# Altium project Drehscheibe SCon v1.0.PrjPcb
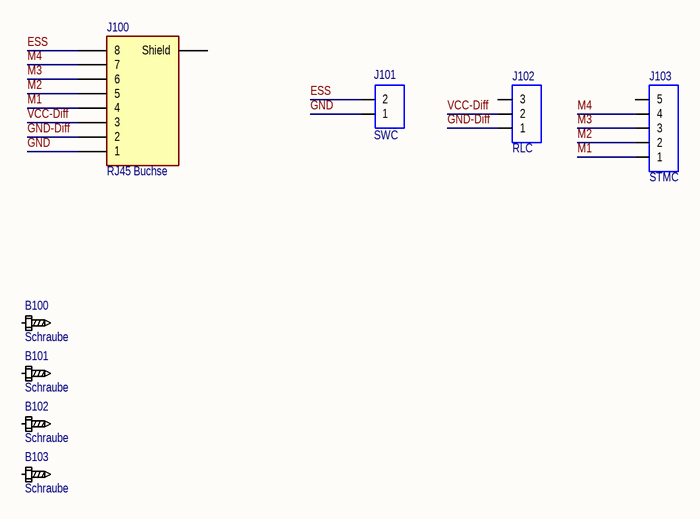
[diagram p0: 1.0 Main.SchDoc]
ZIP: A-3052; Web: www.pcsb.at; Version: v1.0; Title: Drehscheibe SCon; Street: Hauptstraße 47; Phone: 02774/29452; Number: 1; Email: office@pcsb.at; Drawnby2: SONP; Drawnby1: BRAL; Country: Austria; Company: PCSG; Client: Wolfgang Paris, Gerhard Abraham; City: Neustift-Innermanzing
1 sheet, 8 parts. Net scope: global (net labels, ports and power ports of the same name join across sheets).
Board file: PCB1.PcbDoc

## Sheet 1.0 Main.SchDoc: Drehscheibe SCon
size A4; SheetNumber: 1; SheetTotal: 1

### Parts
B100  Schraube  [B_Schraube-M3]
B101  Schraube  [B_Schraube-M3]
B102  Schraube  [B_Schraube-M3]
B103  Schraube  [B_Schraube-M3]
J100  RJ45 Buchse  [J_TE-RJ45-8L-B]
J101  SWC  [SIP-2]
J102  RLC  [Sip-3]
J103  STMC  [SIP-5]

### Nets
ESS: J100.8 J101.2
GND: J100.1 J101.1
GND-Diff: J100.2 J102.1
M1: J100.4 J103.1
M2: J100.5 J103.2
M3: J100.6 J103.3
M4: J100.7 J103.4
VCC-Diff: J100.3 J102.2

Not connected (* = marked no-connect by the designer): B100 1(PAD); B101 1(PAD); B102 1(PAD); B103 1(PAD); J100 MP(Shield); J102 3; J103 5

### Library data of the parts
B100-B103 = B_Schraube: Schraubenloch für M3 Schrauben
J100 = J_RJ45: Connector
J101 = J_THT_CON2: Stecker
J102 = J_THT_CON3: Stecker
J103 = J_THT_CON5: Stecker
